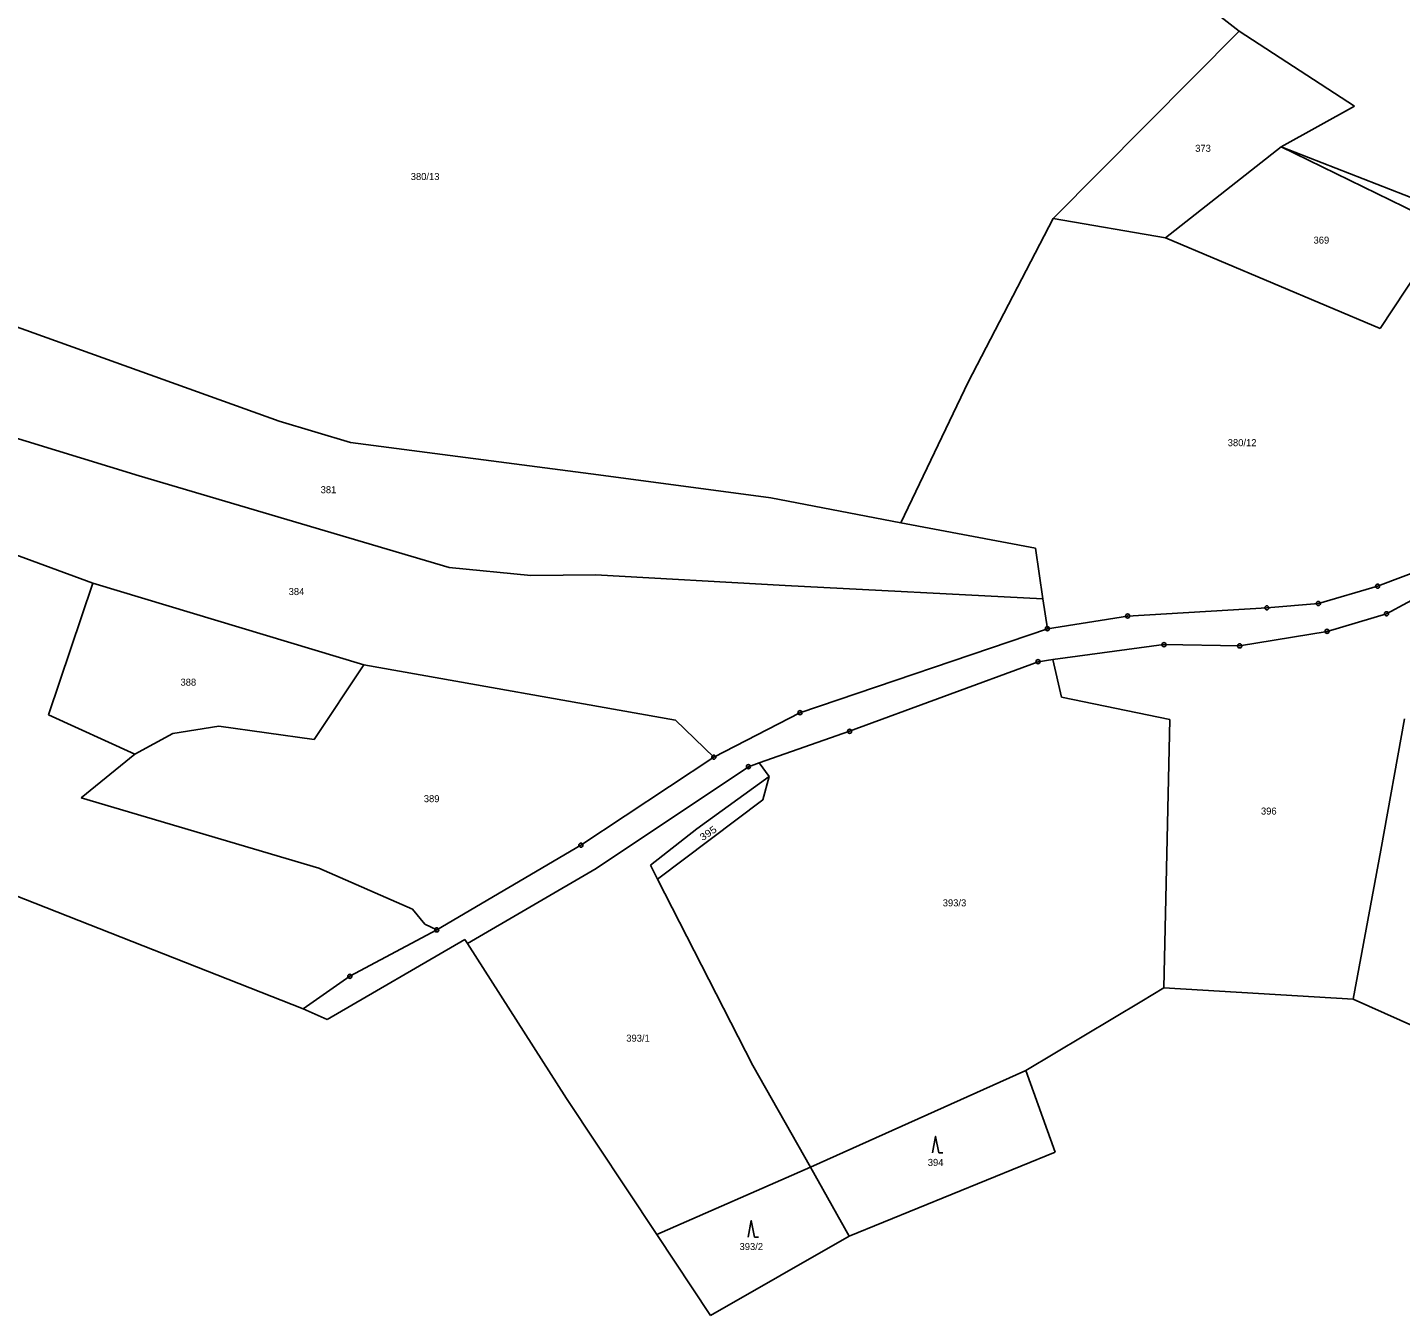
# Model space of a CAD drawing. Extents: x -791548 to -789311, y -1142631 to -1140855.
# Drawn here: x -791085.7 to -790753.3, y -1142523 to -1142211.2 of the extents above; entities that cross this region are included whole.
import ezdxf
from ezdxf.enums import TextEntityAlignment as Align

# ---------------------------------------------------------------- set-up
doc = ezdxf.new("R2010")
doc.units = 0
doc.header["$LTSCALE"] = 0.68
for name, color, linetype, lineweight in [('1', 7, 'Continuous', 25), ('3', 7, 'Continuous', 25), ('8', 7, 'Continuous', 25)]:
    doc.layers.add(name, color=color, linetype=linetype, lineweight=lineweight)
doc.layers.add('2', color=7, linetype='Continuous')

msp = doc.modelspace()

# ---------------------------------------------------------------- linework, layer by layer
at = {"layer": '1'}
for p, q in [((-790802.84, -1142203.93), (-790792.31, -1142212.1)), ((-790792.31, -1142212.1), (-790837.36, -1142257.47)), ((-790792.31, -1142212.1), (-790764.37, -1142230.27)), ((-790764.37, -1142230.27), (-790782.18, -1142240.12)), ((-790810.18, -1142262.19), (-790782.18, -1142240.12)), ((-790782.18, -1142240.12), (-790742.12, -1142259.66)), ((-790739.85, -1142256.67), (-790782.18, -1142240.12)), ((-790837.36, -1142257.47), (-790857.92, -1142297.09)), ((-790810.18, -1142262.19), (-790837.36, -1142257.47)), ((-790742.12, -1142259.66), (-790758.17, -1142284.07)), ((-790758.17, -1142284.07), (-790810.18, -1142262.19)), ((-791024.7, -1142306.52), (-791092.46, -1142282.29)), ((-791058.57, -1142319.74), (-791132.75, -1142297.14)), ((-790857.92, -1142297.09), (-790874.27, -1142331.14)), ((-791007.46, -1142311.66), (-791024.7, -1142306.52)), ((-790947.42, -1142319.55), (-791007.46, -1142311.66)), ((-791137.84, -1142320.79), (-791069.86, -1142345.71)), ((-790983.56, -1142341.93), (-791058.57, -1142319.74)), ((-790905.71, -1142325.13), (-790947.42, -1142319.55)), ((-790874.27, -1142331.14), (-790905.71, -1142325.13)), ((-790841.61, -1142337.24), (-790874.27, -1142331.14)), ((-790839.82, -1142349.57), (-790841.61, -1142337.24)), ((-790963.79, -1142343.89), (-790983.56, -1142341.93)), ((-790948.18, -1142343.72), (-790963.79, -1142343.89)), ((-790902.2, -1142346.31), (-790948.18, -1142343.72)), ((-790758.81, -1142346.48), (-790745.29, -1142341.37)), ((-791080.56, -1142377.64), (-791069.86, -1142345.71)), ((-791069.86, -1142345.71), (-791004.23, -1142365.48)), ((-790839.82, -1142349.57), (-790902.2, -1142346.31)), ((-790773.16, -1142350.68), (-790758.81, -1142346.48)), ((-790756.66, -1142353.16), (-790746.5, -1142347.69)), ((-790838.76, -1142356.78), (-790839.82, -1142349.57)), ((-790785.63, -1142351.72), (-790773.16, -1142350.68)), ((-790838.76, -1142356.78), (-790819.34, -1142353.71)), ((-790819.34, -1142353.71), (-790785.63, -1142351.72)), ((-790771.05, -1142357.42), (-790756.66, -1142353.16)), ((-790898.64, -1142377.11), (-790838.76, -1142356.78)), ((-790792.22, -1142360.93), (-790771.05, -1142357.42)), ((-790837.43, -1142364.26), (-790810.53, -1142360.62)), ((-790810.53, -1142360.62), (-790792.22, -1142360.93)), ((-790841.02, -1142364.76), (-790837.43, -1142364.26)), ((-790835.32, -1142373.32), (-790837.43, -1142364.26)), ((-791016.26, -1142383.59), (-791004.23, -1142365.48)), ((-791004.23, -1142365.48), (-790928.74, -1142378.89)), ((-790886.63, -1142381.6), (-790841.02, -1142364.76)), ((-790809.09, -1142378.74), (-790835.32, -1142373.32)), ((-790919.5, -1142387.87), (-790898.64, -1142377.11)), ((-791059.68, -1142387.16), (-791080.56, -1142377.64)), ((-791050.5, -1142382.1), (-791039.32, -1142380.36)), ((-791039.32, -1142380.36), (-791016.26, -1142383.59)), ((-790928.74, -1142378.89), (-790919.5, -1142387.87)), ((-790810.57, -1142443.72), (-790809.09, -1142378.74)), ((-790758.06, -1142410.4), (-790752.27, -1142378.61)), ((-791059.68, -1142387.16), (-791050.5, -1142382.1)), ((-790908.5, -1142389.25), (-790886.63, -1142381.6)), ((-791072.65, -1142397.72), (-791059.68, -1142387.16)), ((-790951.68, -1142409.17), (-790919.5, -1142387.87)), ((-790947.95, -1142414.79), (-790911.13, -1142390.17)), ((-790911.13, -1142390.17), (-790908.5, -1142389.25)), ((-790923.58, -1142405.18), (-790906.1, -1142392.54)), ((-791015.13, -1142414.76), (-791072.65, -1142397.72)), ((-790933.13, -1142417.39), (-790907.67, -1142398.19)), ((-790934.85, -1142414.03), (-790923.58, -1142405.18)), ((-790986.57, -1142429.67), (-790951.68, -1142409.17)), ((-790764.75, -1142446.47), (-790758.06, -1142410.4)), ((-790933.13, -1142417.39), (-790934.85, -1142414.03)), ((-790992.48, -1142424.69), (-791015.13, -1142414.76)), ((-790979.14, -1142432.93), (-790947.95, -1142414.79)), ((-790910.06, -1142462.51), (-790933.13, -1142417.39)), ((-791091.42, -1142420.26), (-791018.89, -1142448.81)), ((-790989.44, -1142428.32), (-790992.48, -1142424.69)), ((-791007.62, -1142440.9), (-790986.57, -1142429.67)), ((-790986.57, -1142429.67), (-790989.44, -1142428.32)), ((-791013.14, -1142451.38), (-790979.77, -1142431.96)), ((-790979.77, -1142431.96), (-790979.14, -1142432.93)), ((-790979.14, -1142432.93), (-790955.14, -1142470.47)), ((-791018.89, -1142448.81), (-791007.62, -1142440.9)), ((-790810.57, -1142443.72), (-790815.92, -1142446.93)), ((-790764.75, -1142446.47), (-790810.57, -1142443.72)), ((-790815.92, -1142446.93), (-790843.94, -1142463.72)), ((-790719.86, -1142466.43), (-790764.75, -1142446.47)), ((-791018.89, -1142448.81), (-791013.14, -1142451.38)), ((-790896.08, -1142487.07), (-790910.06, -1142462.51)), ((-790896.08, -1142487.07), (-790843.94, -1142463.72)), ((-790843.94, -1142463.72), (-790836.84, -1142483.48)), ((-790933.31, -1142503.4), (-790955.14, -1142470.47)), ((-790836.84, -1142483.48), (-790886.71, -1142503.81)), ((-790933.31, -1142503.4), (-790896.08, -1142487.07)), ((-790896.08, -1142487.07), (-790886.71, -1142503.81)), ((-790920.3, -1142523.02), (-790933.31, -1142503.4)), ((-790886.71, -1142503.81), (-790920.3, -1142523.02))]:
    msp.add_line(p, q, dxfattribs=at)
msp.add_lwpolyline([(-790907.67, -1142398.19), (-790906.1, -1142392.54), (-790908.5, -1142389.25)], dxfattribs=at)
at = {"layer": '3'}
for p, q in [((-790865.06, -1142483.67), (-790864.064, -1142483.67)), ((-790909.68, -1142504.04), (-790908.684, -1142504.04))]:
    msp.add_line(p, q, dxfattribs=at)
for points in [[(-790865.06, -1142483.67), (-790865.81, -1142479.67), (-790866.56, -1142483.67)], [(-790909.68, -1142504.04), (-790910.43, -1142500.04), (-790911.18, -1142504.04)]]:
    msp.add_lwpolyline(points, dxfattribs=at)
at = {"layer": '8'}
for centre, radius in [((-790758.8099, -1142346.48), 0.5), ((-790758.8099, -1142346.48), 0.0303), ((-790773.1599, -1142350.68), 0.5), ((-790773.1599, -1142350.68), 0.0303), ((-790819.3399, -1142353.71), 0.5), ((-790819.3399, -1142353.71), 0.0303), ((-790785.6299, -1142351.72), 0.5), ((-790785.6299, -1142351.72), 0.0303), ((-790756.6599, -1142353.16), 0.5), ((-790756.6599, -1142353.16), 0.0303), ((-790838.7599, -1142356.78), 0.5), ((-790838.7599, -1142356.78), 0.0303), ((-790771.0499, -1142357.42), 0.5), ((-790771.0499, -1142357.42), 0.0303), ((-790810.5299, -1142360.62), 0.5), ((-790810.5299, -1142360.62), 0.0303), ((-790792.2199, -1142360.93), 0.5), ((-790792.2199, -1142360.93), 0.0303), ((-790841.0199, -1142364.76), 0.5), ((-790841.0199, -1142364.76), 0.0303), ((-790898.6399, -1142377.11), 0.5), ((-790898.6399, -1142377.11), 0.0303), ((-790886.6299, -1142381.6), 0.5), ((-790886.6299, -1142381.6), 0.0303), ((-790919.4999, -1142387.87), 0.5), ((-790919.4999, -1142387.87), 0.0303), ((-790911.1299, -1142390.17), 0.5), ((-790911.1299, -1142390.17), 0.0303), ((-790951.6799, -1142409.17), 0.5), ((-790951.6799, -1142409.17), 0.0303), ((-790986.5699, -1142429.67), 0.5), ((-790986.5699, -1142429.67), 0.0303), ((-791007.6199, -1142440.9), 0.5), ((-791007.6199, -1142440.9), 0.0303)]:
    msp.add_circle(centre, radius, dxfattribs=at)

# ---------------------------------------------------------------- texts
at = {"layer": '2'}
for s, p in [('373', (-790801.079, -1142241.332)), ('380/13', (-790989.39, -1142248.172)), ('369', (-790772.429, -1142263.562)), ('380/12', (-790791.62, -1142312.592)), ('381', (-791012.779, -1142323.972)), ('384', (-791020.529, -1142348.632)), ('388', (-791046.709, -1142370.562)), ('389', (-790987.809, -1142398.762)), ('396', (-790785.159, -1142401.762)), ('393/3', (-790861.24, -1142423.982)), ('393/1', (-790937.85, -1142456.732)), ('394', (-790865.809, -1142486.802)), ('393/2', (-790910.43, -1142507.172))]:
    msp.add_text(s, height=1.7, dxfattribs=at).set_placement(p, align=Align.CENTER)
at = {"layer": '2', "width": 1.15}
msp.add_text('395', height=1.7, rotation=34, dxfattribs=at).set_placement((-790920.4103, -1142406.9794), align=Align.CENTER)

doc.saveas('drawing.dxf')
